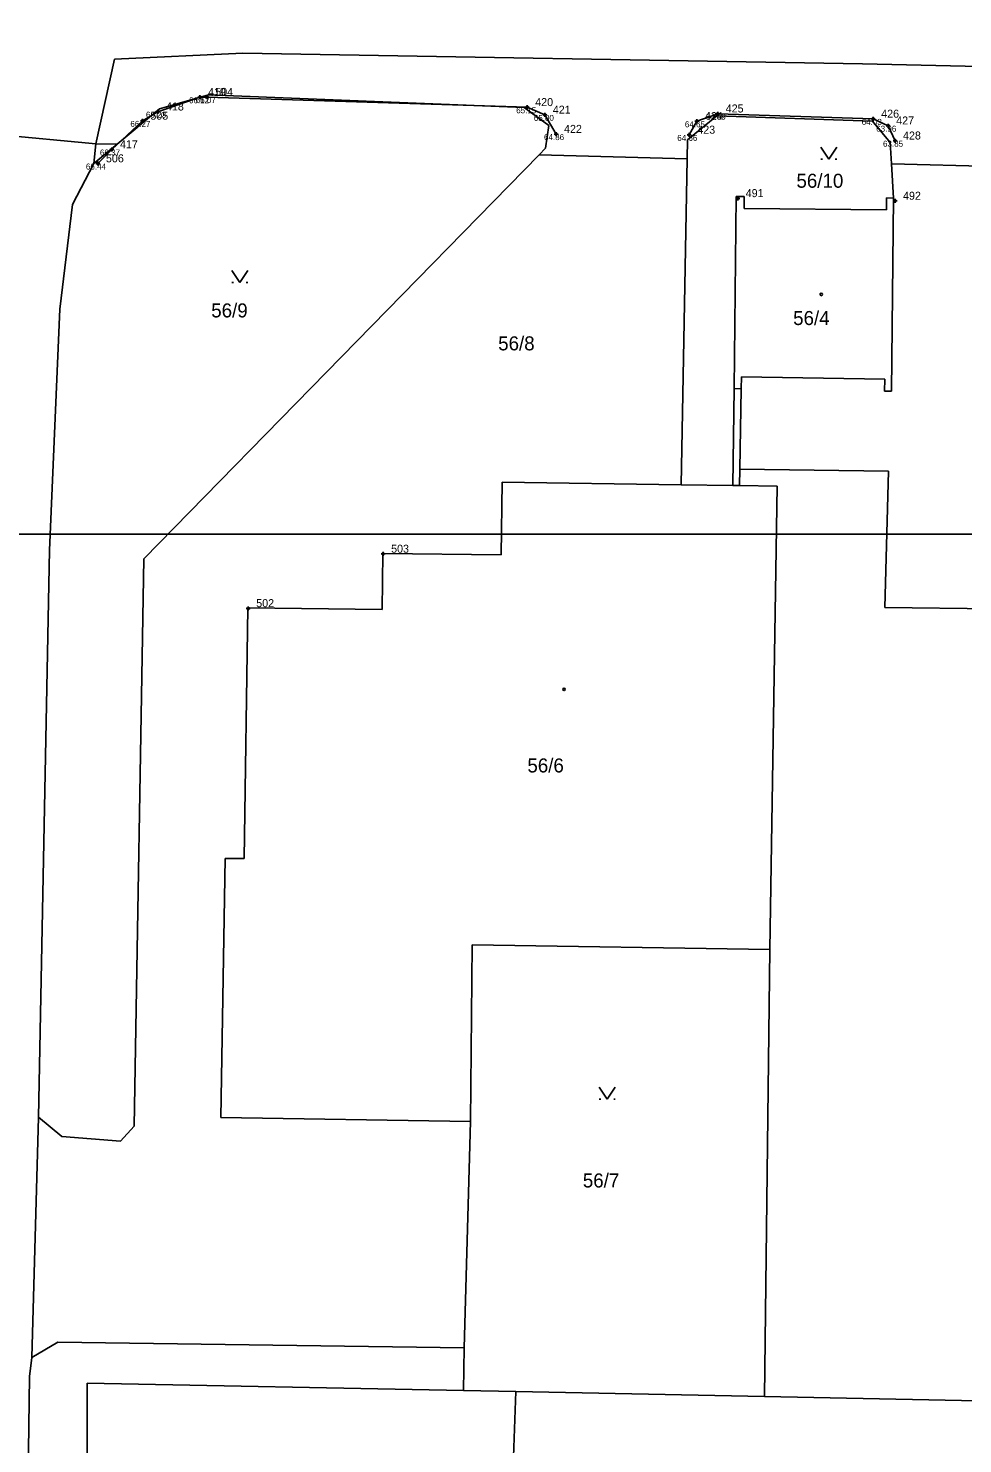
# Model space of a CAD drawing. Extents: x -454285 to -453563, y -1108687 to -1108249.
# Drawn here: x -453869.2 to -453822.5, y -1108547.2 to -1108476.5 of the extents above; entities that cross this region are included whole.
import ezdxf

# ---------------------------------------------------------------- set-up
doc = ezdxf.new("R2010")
doc.units = 0
for name, color, linetype in [('1', 7, 'Continuous'), ('14', 7, 'Continuous'), ('15', 7, 'Continuous'), ('2', 7, 'Continuous'), ('23', 7, 'Continuous'), ('25', 7, 'Continuous'), ('BODY_T1_2018', 7, 'Continuous'), ('CISLA_T1_2018', 7, 'Continuous'), ('okraj asf.komunikace', 7, 'Continuous'), ('rámy', 7, 'Continuous'), ('VYSKY_T1_2018', 7, 'Continuous')]:
    doc.layers.add(name, color=color, linetype=linetype)

# ---------------------------------------------------------------- blocks, each defined once
blk = doc.blocks.new('Z402')
for start, end in [(0, 180), (180, 0)]:
    blk.add_arc((0, 0), 0.15, start, end)
blk = doc.blocks.new('Z3140')
for p, q in [((-1, 1.5), (0, 0)), ((-1, 0), (-0.8, 0)), ((0, 0), (1, 1.5)), ((0.8, 0), (1, 0))]:
    blk.add_line(p, q)
blk = doc.blocks.new('POINT_DISPLAY')
for p, q in [((-0.1, 0), (0.1, 0)), ((0, -0.1), (0, 0.1))]:
    blk.add_line(p, q)
blk.add_circle((0, 0), 0.05)
blk = doc.blocks.new('t1_2018')
at = {"layer": 'BODY_T1_2018'}
for p in [(-453860.63, -1108479.93), (-453860.27, -1108479.92), (-453844.28, -1108480.43), (-453863.51, -1108481.11), (-453862.73, -1108480.65), (-453843.4, -1108480.81), (-453835.8, -1108481.13), (-453834.76, -1108480.75), (-453826.99, -1108481.01), (-453842.84, -1108481.77), (-453836.18, -1108481.81), (-453826.24, -1108481.35), (-453865.03, -1108482.54), (-453825.9, -1108482.1), (-453865.73, -1108483.24), (-453833.76, -1108484.98), (-453825.9, -1108485.11), (-453851.48, -1108502.75), (-453858.22, -1108505.47)]:
    blk.add_blockref('POINT_DISPLAY', p, dxfattribs=at)
at = {"layer": 'CISLA_T1_2018'}
for s, p in [('419', (-453860.23, -1108479.87)), ('504', (-453859.87, -1108479.86)), ('418', (-453862.33, -1108480.59)), ('420', (-453843.88, -1108480.37)), ('421', (-453843, -1108480.75)), ('425', (-453834.36, -1108480.69)), ('505', (-453863.11, -1108481.05)), ('424', (-453835.4, -1108481.07)), ('426', (-453826.59, -1108480.95)), ('427', (-453825.84, -1108481.29)), ('422', (-453842.44, -1108481.71)), ('423', (-453835.78, -1108481.75)), ('428', (-453825.5, -1108482.04)), ('417', (-453864.63, -1108482.48)), ('506', (-453865.33, -1108483.18)), ('491', (-453833.36, -1108484.92)), ('492', (-453825.5, -1108485.05)), ('503', (-453851.08, -1108502.69)), ('502', (-453857.82, -1108505.41))]:
    blk.add_text(s, height=0.4, dxfattribs=at).set_placement(p)
at = {"layer": 'VYSKY_T1_2018'}
for s, p in [('66.12', (-453861.18, -1108480.23)), ('66.07', (-453860.845, -1108480.22)), ('66.23', (-453863.33, -1108480.95)), ('65.15', (-453844.83, -1108480.73)), ('65.00', (-453843.95, -1108481.11)), ('64.59', (-453835.36, -1108481.05)), ('64.03', (-453827.565, -1108481.31)), ('66.27', (-453864.11, -1108481.41)), ('64.86', (-453843.44, -1108482.07)), ('64.65', (-453836.4, -1108481.43)), ('63.96', (-453826.84, -1108481.65)), ('64.66', (-453836.78, -1108482.11)), ('63.85', (-453826.5, -1108482.4)), ('66.37', (-453865.63, -1108482.84)), ('66.44', (-453866.33, -1108483.54))]:
    blk.add_text(s, height=0.3, dxfattribs=at).set_placement(p)

msp = doc.modelspace()

# ---------------------------------------------------------------- linework, layer by layer
at = {"layer": '1'}
for p, q in [((-453860.197, -1108479.801), (-453862.647, -1108480.511)), ((-453844.437, -1108480.441), (-453860.197, -1108479.801)), ((-453864.777, -1108482.281), (-453862.647, -1108480.511)), ((-453843.197, -1108481.341), (-453844.437, -1108480.441)), ((-453834.797, -1108480.851), (-453836.267, -1108482.051)), ((-453827.027, -1108481.121), (-453834.797, -1108480.851)), ((-453871.267, -1108481.741), (-453865.837, -1108482.251)), ((-453843.357, -1108482.471), (-453843.197, -1108481.341)), ((-453826.137, -1108482.191), (-453827.027, -1108481.121)), ((-453865.937, -1108483.241), (-453864.777, -1108482.281)), ((-453865.837, -1108482.251), (-453864.777, -1108482.281)), ((-453843.687, -1108482.811), (-453843.357, -1108482.471)), ((-453836.267, -1108482.051), (-453836.287, -1108483.001)), ((-453826.137, -1108482.191), (-453826.077, -1108483.251)), ((-453863.437, -1108503.001), (-453843.687, -1108482.811)), ((-453836.287, -1108483.001), (-453843.687, -1108482.811)), ((-453836.287, -1108483.001), (-453836.587, -1108499.291)), ((-453865.937, -1108483.241), (-453867.007, -1108485.291)), ((-453811.157, -1108483.631), (-453826.077, -1108483.251)), ((-453826.077, -1108483.251), (-453825.977, -1108484.971)), ((-453867.007, -1108485.291), (-453867.627, -1108490.521)), ((-453833.837, -1108484.881), (-453833.937, -1108494.491)), ((-453833.437, -1108484.881), (-453833.837, -1108484.881)), ((-453833.437, -1108485.481), (-453833.437, -1108484.881)), ((-453825.977, -1108484.971), (-453826.327, -1108484.961)), ((-453826.327, -1108484.961), (-453826.327, -1108485.561)), ((-453826.077, -1108494.621), (-453825.977, -1108484.971)), ((-453826.327, -1108485.561), (-453833.437, -1108485.481)), ((-453867.627, -1108490.521), (-453868.157, -1108502.561)), ((-453833.937, -1108494.491), (-453833.997, -1108499.331)), ((-453833.657, -1108498.511), (-453833.587, -1108494.501)), ((-453833.577, -1108493.901), (-453833.587, -1108494.501)), ((-453826.417, -1108494.011), (-453833.577, -1108493.901)), ((-453826.427, -1108494.611), (-453826.417, -1108494.011)), ((-453826.077, -1108494.621), (-453826.427, -1108494.611)), ((-453833.667, -1108499.331), (-453833.657, -1108498.511)), ((-453833.657, -1108498.511), (-453826.227, -1108498.611)), ((-453826.417, -1108505.431), (-453826.227, -1108498.611)), ((-453845.577, -1108502.801), (-453845.527, -1108499.161)), ((-453836.587, -1108499.291), (-453845.527, -1108499.161)), ((-453836.587, -1108499.291), (-453833.997, -1108499.331)), ((-453833.997, -1108499.331), (-453833.667, -1108499.331)), ((-453833.667, -1108499.331), (-453831.787, -1108499.361)), ((-453832.157, -1108522.521), (-453831.787, -1108499.361)), ((-453868.157, -1108502.561), (-453868.697, -1108530.891)), ((-453863.927, -1108531.341), (-453863.437, -1108503.001)), ((-453851.527, -1108505.531), (-453851.497, -1108502.731)), ((-453851.497, -1108502.731), (-453845.577, -1108502.801)), ((-453858.247, -1108505.451), (-453858.427, -1108517.971)), ((-453858.247, -1108505.451), (-453851.527, -1108505.531)), ((-453813.187, -1108505.601), (-453826.417, -1108505.431)), ((-453859.367, -1108517.971), (-453859.587, -1108530.911)), ((-453858.427, -1108517.971), (-453859.367, -1108517.971)), ((-453847.117, -1108531.121), (-453847.037, -1108522.281)), ((-453847.037, -1108522.281), (-453832.157, -1108522.521)), ((-453832.157, -1108522.521), (-453832.427, -1108544.861)), ((-453869.027, -1108542.901), (-453868.697, -1108530.891)), ((-453868.697, -1108530.891), (-453867.527, -1108531.871)), ((-453859.587, -1108530.911), (-453847.117, -1108531.121)), ((-453847.427, -1108542.421), (-453847.117, -1108531.121)), ((-453867.527, -1108531.871), (-453864.607, -1108532.091)), ((-453864.607, -1108532.091), (-453863.927, -1108531.341)), ((-453867.737, -1108542.141), (-453869.027, -1108542.901)), ((-453867.737, -1108542.141), (-453847.427, -1108542.421)), ((-453847.467, -1108544.561), (-453847.427, -1108542.421)), ((-453847.467, -1108544.561), (-453866.267, -1108544.191)), ((-453866.247, -1108559.951), (-453866.267, -1108544.191)), ((-453844.847, -1108544.611), (-453847.467, -1108544.561)), ((-453844.847, -1108544.611), (-453845.237, -1108555.251)), ((-453832.427, -1108544.861), (-453844.847, -1108544.611)), ((-453832.427, -1108544.861), (-453815.917, -1108545.181))]:
    msp.add_line(p, q, dxfattribs=at)
at = {"layer": '2'}
for p, q in [((-453865.837, -1108482.251), (-453864.897, -1108478.031)), ((-453864.897, -1108478.031), (-453858.487, -1108477.731)), ((-453858.487, -1108477.731), (-453827.527, -1108478.261)), ((-453827.527, -1108478.261), (-453764.397, -1108479.731)), ((-453865.837, -1108482.251), (-453865.937, -1108483.241)), ((-453833.937, -1108494.491), (-453833.587, -1108494.501)), ((-453869.147, -1108543.861), (-453869.027, -1108542.901)), ((-453869.727, -1108586.751), (-453869.147, -1108543.861))]:
    msp.add_line(p, q, dxfattribs=at)
at = {"layer": 'okraj asf.komunikace'}
for points in [[(-453865.73, -1108483.24), (-453865.03, -1108482.54), (-453863.51, -1108481.11), (-453862.73, -1108480.65), (-453860.63, -1108479.93), (-453860.27, -1108479.92), (-453844.28, -1108480.43), (-453843.4, -1108480.81), (-453842.84, -1108481.77)], [(-453836.18, -1108481.81), (-453835.8, -1108481.13), (-453834.76, -1108480.75), (-453826.99, -1108481.01), (-453826.24, -1108481.35), (-453825.9, -1108482.1)]]:
    msp.add_lwpolyline(points, dxfattribs=at)
at = {"layer": 'rámy'}
msp.add_lwpolyline([(-453889.309, -1108441.707), (-453790.141, -1108441.707), (-453790.141, -1108501.759), (-453889.309, -1108501.759)], close=True, dxfattribs=at)

# ---------------------------------------------------------------- block references
msp.add_blockref('t1_2018', (0, 0))
at = {"layer": '23', "xscale": 0.4, "yscale": 0.4000000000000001}
for p in [(-453829.204, -1108483.022), (-453858.637, -1108489.191), (-453840.277, -1108529.991)]:
    msp.add_blockref('Z3140', p, dxfattribs=at)
at = {"layer": '25', "xscale": 0.4, "yscale": 0.4000000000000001}
for p in [(-453829.589, -1108489.784), (-453842.437, -1108509.521)]:
    msp.add_blockref('Z402', p, dxfattribs=at)

# ---------------------------------------------------------------- texts
at = {"layer": '14'}
for s, p in [('56/10', (-453830.825, -1108484.451)), ('56/9', (-453860.068, -1108490.931)), ('56/8', (-453845.729, -1108492.577)), ('56/7', (-453841.5, -1108534.411))]:
    msp.add_text(s, height=0.7, dxfattribs=at).set_placement(p)
at = {"layer": '15'}
for s, p in [('56/4', (-453830.99, -1108491.311)), ('56/6', (-453844.27, -1108513.671))]:
    msp.add_text(s, height=0.7, dxfattribs=at).set_placement(p)

doc.saveas('drawing.dxf')
